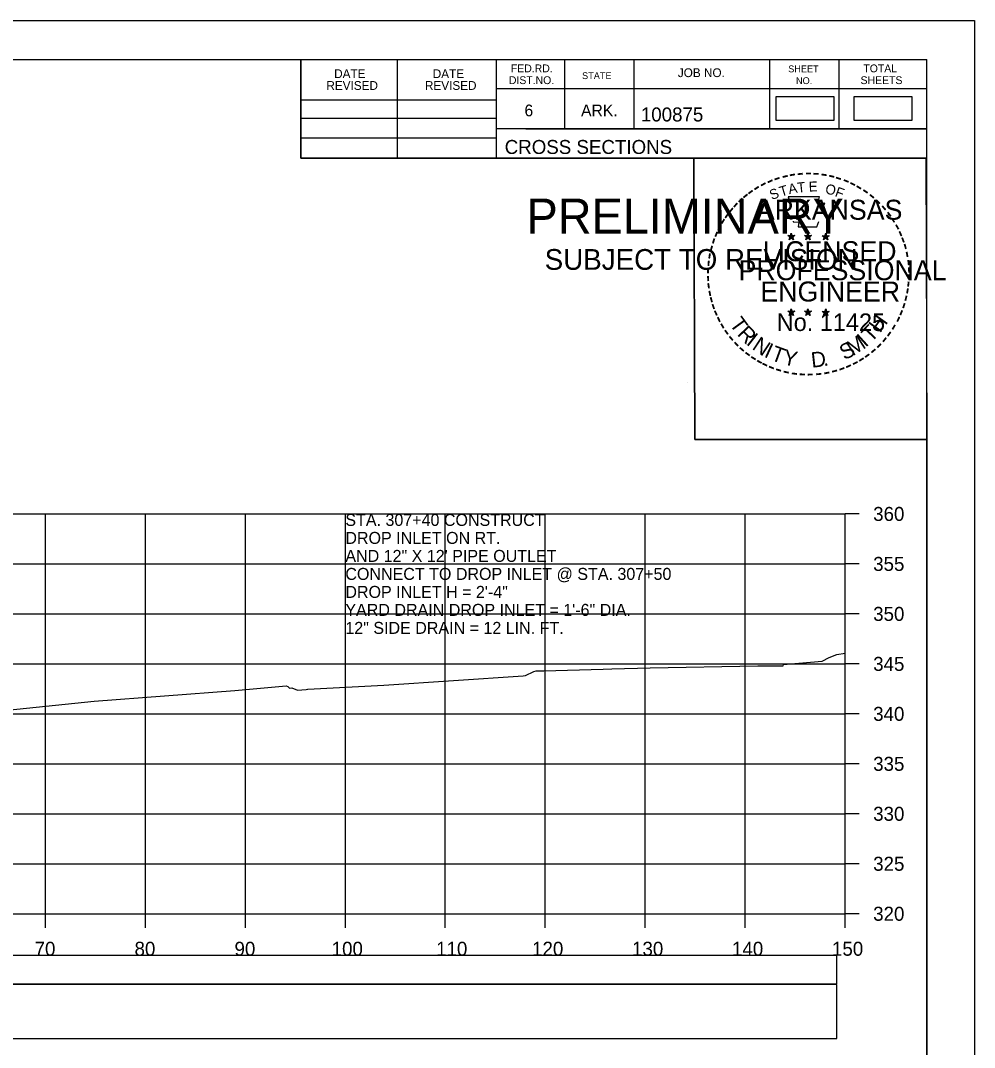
# Model space of a CAD drawing. Extents: x 1368122 to 1710785, y 373130 to 557566.
# Drawn here: x 1369423.1 to 1369518.5, y 373880.9 to 373983.7 of the extents above; entities that cross this region are included whole.
import ezdxf

# ---------------------------------------------------------------- set-up
doc = ezdxf.new("R2010")
doc.units = 0
for name, color, linetype in [('R_Axis', 7, 'Continuous'), ('R_Axis Annot', 7, 'Continuous'), ('R_Border', 7, 'Continuous'), ('R_Border PE', 7, 'Continuous'), ('R_Border Prem', 7, 'Continuous'), ('R_Drive', 7, 'Continuous'), ('R_Exist Surface', 7, 'Continuous'), ('R_Grid', 7, 'Continuous'), ('R_No Plot', 7, 'Continuous'), ('R_Water Annot', 7, 'Continuous')]:
    doc.layers.add(name, color=color, linetype=linetype)

msp = doc.modelspace()

# ---------------------------------------------------------------- linework, layer by layer
for points in [[(1369206.41, 373887.32), (1369504.71, 373887.32), (1369504.71, 373890.13), (1369206.41, 373890.13)], [(1369206.41, 373881.85), (1369504.71, 373881.85), (1369504.71, 373887.26), (1369206.41, 373887.26)]]:
    msp.add_lwpolyline(points, close=True)
at = {"layer": 'R_Axis'}
for p, q in [((1369505.56, 373894.32), (1369505.56, 373934.32)), ((1369506.96, 373934.32), (1369505.56, 373934.32)), ((1369506.96, 373929.32), (1369505.56, 373929.32)), ((1369506.96, 373924.32), (1369505.56, 373924.32)), ((1369506.96, 373919.32), (1369505.56, 373919.32)), ((1369506.96, 373914.32), (1369505.56, 373914.32)), ((1369506.96, 373909.32), (1369505.56, 373909.32)), ((1369506.96, 373904.32), (1369505.56, 373904.32)), ((1369506.96, 373899.32), (1369505.56, 373899.32)), ((1369205.56, 373894.32), (1369505.56, 373894.32)), ((1369425.56, 373892.92), (1369425.56, 373894.32)), ((1369435.56, 373892.92), (1369435.56, 373894.32)), ((1369445.56, 373892.92), (1369445.56, 373894.32)), ((1369455.56, 373892.92), (1369455.56, 373894.32)), ((1369465.56, 373892.92), (1369465.56, 373894.32)), ((1369475.56, 373892.92), (1369475.56, 373894.32)), ((1369485.56, 373892.92), (1369485.56, 373894.32)), ((1369495.56, 373892.92), (1369495.56, 373894.32)), ((1369505.56, 373892.92), (1369505.56, 373894.32)), ((1369506.96, 373894.32), (1369505.56, 373894.32))]:
    msp.add_line(p, q, dxfattribs=at)
at = {"layer": 'R_Border'}
for p, q in [((1369197.56, 373979.78), (1369513.74, 373979.78)), ((1369451.1, 373969.9), (1369451.1, 373979.78)), ((1369460.78, 373969.9), (1369460.78, 373979.78)), ((1369470.64, 373979.78), (1369470.64, 373969.9)), ((1369477.48, 373979.78), (1369477.48, 373972.84)), ((1369484.42, 373979.78), (1369484.42, 373972.84)), ((1369498, 373979.78), (1369498, 373972.84)), ((1369504.94, 373979.78), (1369504.94, 373972.84)), ((1369513.74, 373774.32), (1369513.74, 373979.78)), ((1369513.74, 373976.84), (1369470.64, 373976.84)), ((1369513.74, 373976.86), (1369513.74, 373976.86)), ((1369451.1, 373975.76), (1369470.64, 373975.76)), ((1369451.1, 373973.9), (1369470.64, 373973.9)), ((1369513.74, 373972.84), (1369470.64, 373972.84)), ((1369473.6, 373972.84), (1369513.74, 373972.84)), ((1369451.1, 373971.96), (1369470.64, 373971.96)), ((1369513.74, 373969.9), (1369451.1, 373969.9))]:
    msp.add_line(p, q, dxfattribs=at)
at = {"layer": 'R_Border PE'}
for p, q in [((1369500.17, 373962.41), (1369500.13, 373962.16)), ((1369500.17, 373962.05), (1369500.17, 373962.41)), ((1369500.17, 373962.41), (1369500.22, 373962.16)), ((1369501.84, 373962.41), (1369501.8, 373962.16)), ((1369501.84, 373962.05), (1369501.84, 373962.41)), ((1369501.84, 373962.41), (1369501.89, 373962.16)), ((1369503.61, 373962.4), (1369503.57, 373962.15)), ((1369503.61, 373962.04), (1369503.61, 373962.4)), ((1369503.61, 373962.4), (1369503.66, 373962.15)), ((1369499.83, 373962.16), (1369500.17, 373962.05)), ((1369499.83, 373962.16), (1369500.08, 373962.11)), ((1369499.83, 373962.16), (1369500.06, 373962.04)), ((1369499.96, 373961.75), (1369500.17, 373962.05)), ((1369499.96, 373961.75), (1369500.08, 373961.99)), ((1369499.96, 373961.75), (1369500.17, 373961.97)), ((1369500.52, 373962.16), (1369500.17, 373962.05)), ((1369500.39, 373961.75), (1369500.17, 373962.05)), ((1369500.39, 373961.75), (1369500.17, 373961.96)), ((1369500.52, 373962.16), (1369500.24, 373962.11)), ((1369500.39, 373961.75), (1369500.25, 373962.04)), ((1369500.52, 373962.16), (1369500.32, 373962.06)), ((1369501.5, 373962.16), (1369501.84, 373962.05)), ((1369501.5, 373962.16), (1369501.75, 373962.11)), ((1369501.5, 373962.16), (1369501.73, 373962.04)), ((1369501.63, 373961.75), (1369501.84, 373962.05)), ((1369501.63, 373961.75), (1369501.75, 373961.99)), ((1369501.63, 373961.75), (1369501.84, 373961.97)), ((1369502.19, 373962.16), (1369501.84, 373962.05)), ((1369502.06, 373961.75), (1369501.84, 373962.05)), ((1369502.06, 373961.75), (1369501.84, 373961.96)), ((1369502.19, 373962.16), (1369501.91, 373962.11)), ((1369502.06, 373961.75), (1369501.92, 373962.04)), ((1369502.19, 373962.16), (1369501.99, 373962.06)), ((1369503.26, 373962.15), (1369503.61, 373962.04)), ((1369503.26, 373962.15), (1369503.51, 373962.1)), ((1369503.26, 373962.15), (1369503.5, 373962.02)), ((1369503.39, 373961.74), (1369503.61, 373962.04)), ((1369503.39, 373961.74), (1369503.52, 373961.98)), ((1369503.39, 373961.74), (1369503.61, 373961.96)), ((1369503.96, 373962.15), (1369503.61, 373962.04)), ((1369503.82, 373961.74), (1369503.61, 373962.04)), ((1369503.82, 373961.74), (1369503.61, 373961.95)), ((1369503.96, 373962.15), (1369503.67, 373962.1)), ((1369503.82, 373961.74), (1369503.68, 373962.03)), ((1369503.96, 373962.15), (1369503.75, 373962.04)), ((1369499.82, 373954.59), (1369500.17, 373954.47)), ((1369499.82, 373954.59), (1369500.07, 373954.54)), ((1369499.82, 373954.59), (1369500.06, 373954.46)), ((1369499.95, 373954.18), (1369500.17, 373954.47)), ((1369499.95, 373954.18), (1369500.08, 373954.42)), ((1369499.95, 373954.18), (1369500.17, 373954.39)), ((1369500.17, 373954.84), (1369500.13, 373954.59)), ((1369500.17, 373954.47), (1369500.17, 373954.84)), ((1369500.17, 373954.84), (1369500.22, 373954.59)), ((1369500.52, 373954.59), (1369500.17, 373954.47)), ((1369500.38, 373954.18), (1369500.17, 373954.47)), ((1369500.38, 373954.18), (1369500.17, 373954.39)), ((1369500.52, 373954.59), (1369500.23, 373954.54)), ((1369500.38, 373954.18), (1369500.25, 373954.47)), ((1369500.52, 373954.59), (1369500.31, 373954.48)), ((1369501.49, 373954.59), (1369501.84, 373954.47)), ((1369501.49, 373954.59), (1369501.74, 373954.54)), ((1369501.49, 373954.59), (1369501.73, 373954.46)), ((1369501.62, 373954.18), (1369501.84, 373954.47)), ((1369501.62, 373954.18), (1369501.75, 373954.42)), ((1369501.62, 373954.18), (1369501.84, 373954.39)), ((1369501.84, 373954.84), (1369501.8, 373954.59)), ((1369501.84, 373954.47), (1369501.84, 373954.84)), ((1369501.84, 373954.84), (1369501.89, 373954.59)), ((1369502.19, 373954.59), (1369501.84, 373954.47)), ((1369502.05, 373954.18), (1369501.84, 373954.47)), ((1369502.05, 373954.18), (1369501.84, 373954.39)), ((1369502.19, 373954.59), (1369501.9, 373954.54)), ((1369502.05, 373954.18), (1369501.92, 373954.47)), ((1369502.19, 373954.59), (1369501.98, 373954.48)), ((1369503.26, 373954.58), (1369503.61, 373954.46)), ((1369503.26, 373954.58), (1369503.51, 373954.53)), ((1369503.26, 373954.58), (1369503.49, 373954.45)), ((1369503.39, 373954.17), (1369503.61, 373954.46)), ((1369503.39, 373954.17), (1369503.52, 373954.41)), ((1369503.39, 373954.17), (1369503.6, 373954.38)), ((1369503.61, 373954.83), (1369503.57, 373954.58)), ((1369503.82, 373954.17), (1369503.6, 373954.38)), ((1369503.61, 373954.46), (1369503.61, 373954.83)), ((1369503.61, 373954.83), (1369503.66, 373954.58)), ((1369503.95, 373954.58), (1369503.61, 373954.46)), ((1369503.82, 373954.17), (1369503.61, 373954.46)), ((1369503.95, 373954.58), (1369503.67, 373954.53)), ((1369503.82, 373954.17), (1369503.68, 373954.46)), ((1369503.95, 373954.58), (1369503.75, 373954.47))]:
    msp.add_line(p, q, dxfattribs=at)
for points in [[(1369499.87, 373966.04), (1369500.14, 373965.21)], [(1369503.38, 373965.11), (1369503.52, 373965.4), (1369502.83, 373965.37), (1369502.98, 373966.04), (1369499.87, 373966.04)], [(1369500.36, 373963.61), (1369500.36, 373963.53), (1369500.92, 373963.51), (1369500.87, 373963.03), (1369502.74, 373963.03), (1369502.94, 373963.57)], [(1369500.17, 373962.41), (1369500.39, 373961.75), (1369499.83, 373962.16), (1369500.52, 373962.16), (1369499.96, 373961.75), (1369500.17, 373962.41)], [(1369501.84, 373962.41), (1369502.06, 373961.75), (1369501.5, 373962.16), (1369502.19, 373962.16), (1369501.63, 373961.75), (1369501.84, 373962.41)], [(1369503.61, 373962.4), (1369503.82, 373961.74), (1369503.26, 373962.15), (1369503.96, 373962.15), (1369503.39, 373961.74), (1369503.61, 373962.4)], [(1369500.17, 373954.84), (1369500.38, 373954.18), (1369499.82, 373954.59), (1369500.52, 373954.59), (1369499.95, 373954.18), (1369500.17, 373954.84)], [(1369501.84, 373954.84), (1369502.05, 373954.18), (1369501.49, 373954.59), (1369502.19, 373954.59), (1369501.62, 373954.18), (1369501.84, 373954.84)], [(1369503.61, 373954.83), (1369503.82, 373954.17), (1369503.26, 373954.58), (1369503.95, 373954.58), (1369503.39, 373954.17), (1369503.61, 373954.83)]]:
    msp.add_lwpolyline(points, dxfattribs=at)
for centre, radius in [((1369500.17, 373962.05), 0.172), ((1369500.17, 373962.05), 0.145), ((1369501.84, 373962.05), 0.172), ((1369501.84, 373962.05), 0.145), ((1369503.61, 373962.03), 0.172), ((1369503.61, 373962.03), 0.145), ((1369500.17, 373962.05), 0.116), ((1369500.17, 373962.05), 0.0991), ((1369500.17, 373962.05), 0.0747), ((1369500.17, 373962.05), 0.0495), ((1369500.17, 373962.05), 0.0296), ((1369501.84, 373962.05), 0.116), ((1369501.84, 373962.05), 0.0991), ((1369501.84, 373962.05), 0.0747), ((1369501.84, 373962.05), 0.0495), ((1369501.84, 373962.05), 0.0296), ((1369503.61, 373962.03), 0.116), ((1369503.61, 373962.03), 0.0991), ((1369503.61, 373962.03), 0.0747), ((1369503.61, 373962.03), 0.0495), ((1369503.61, 373962.03), 0.0296), ((1369500.17, 373954.47), 0.172), ((1369500.17, 373954.47), 0.145), ((1369500.17, 373954.47), 0.116), ((1369500.17, 373954.47), 0.0991), ((1369500.17, 373954.47), 0.0747), ((1369500.17, 373954.47), 0.0495), ((1369500.17, 373954.47), 0.0296), ((1369501.84, 373954.47), 0.172), ((1369501.84, 373954.47), 0.145), ((1369501.84, 373954.47), 0.116), ((1369501.84, 373954.47), 0.0991), ((1369501.84, 373954.47), 0.0747), ((1369501.84, 373954.47), 0.0495), ((1369501.84, 373954.47), 0.0296), ((1369503.61, 373954.46), 0.172), ((1369503.61, 373954.46), 0.145), ((1369503.61, 373954.46), 0.116), ((1369503.61, 373954.46), 0.0991), ((1369503.61, 373954.46), 0.0747), ((1369503.61, 373954.46), 0.0495), ((1369503.61, 373954.46), 0.0296)]:
    msp.add_circle(centre, radius, dxfattribs=at)
at = {"layer": 'R_Drive'}
for points in [[(1369498.61, 373973.72), (1369504.45, 373973.72), (1369504.45, 373976.03), (1369498.61, 373976.03)], [(1369506.42, 373973.72), (1369512.26, 373973.72), (1369512.26, 373976.03), (1369506.42, 373976.03)]]:
    msp.add_lwpolyline(points, close=True, dxfattribs=at)
at = {"layer": 'R_Exist Surface'}
msp.add_lwpolyline([(1369420.72, 373914.58), (1369430.42, 373915.58), (1369444.49, 373916.66), (1369449.64, 373917.11), (1369449.82, 373917.04), (1369449.98, 373916.9), (1369450.19, 373916.91), (1369450.76, 373916.69), (1369451.64, 373916.77), (1369451.78, 373916.79), (1369451.79, 373916.79), (1369459.41, 373917.2), (1369473.34, 373918.12), (1369473.57, 373918.16), (1369474.4, 373918.56), (1369474.4, 373918.56), (1369474.66, 373918.63), (1369474.67, 373918.64), (1369474.68, 373918.64), (1369475.41, 373918.64), (1369481.34, 373918.78), (1369482.21, 373918.81), (1369486.06, 373918.93), (1369496.83, 373919.11), (1369497.87, 373919.12), (1369499.34, 373919.13), (1369499.39, 373919.26), (1369499.39, 373919.28), (1369499.75, 373919.28), (1369503.27, 373919.6), (1369503.95, 373919.96), (1369504.74, 373920.27), (1369505.56, 373920.38)], dxfattribs=at)
at = {"layer": 'R_Grid'}
for p, q in [((1369205.56, 373934.32), (1369505.56, 373934.32)), ((1369425.56, 373894.32), (1369425.56, 373934.32)), ((1369435.56, 373894.32), (1369435.56, 373934.32)), ((1369445.56, 373894.32), (1369445.56, 373934.32)), ((1369455.56, 373894.32), (1369455.56, 373934.32)), ((1369465.56, 373894.32), (1369465.56, 373934.32)), ((1369475.56, 373894.32), (1369475.56, 373934.32)), ((1369485.56, 373894.32), (1369485.56, 373934.32)), ((1369495.56, 373894.32), (1369495.56, 373934.32)), ((1369505.56, 373894.32), (1369505.56, 373934.32)), ((1369205.56, 373929.32), (1369505.56, 373929.32)), ((1369205.56, 373924.32), (1369505.56, 373924.32)), ((1369205.56, 373919.32), (1369505.56, 373919.32)), ((1369205.56, 373914.32), (1369505.56, 373914.32)), ((1369205.56, 373909.32), (1369505.56, 373909.32)), ((1369205.56, 373904.32), (1369505.56, 373904.32)), ((1369205.56, 373899.32), (1369505.56, 373899.32)), ((1369205.56, 373894.32), (1369505.56, 373894.32))]:
    msp.add_line(p, q, dxfattribs=at)
at = {"layer": 'R_No Plot'}
for p, q in [((1369185.16, 373983.68), (1369518.49, 373983.68)), ((1369489.77, 373947.45), (1369489.77, 373947.45))]:
    msp.add_line(p, q, dxfattribs=at)
for points in [[(1369185.15, 373983.68), (1369518.49, 373983.68), (1369518.49, 373770.34), (1369185.15, 373770.34)], [(1369431.48, 373979.78), (1369451.1, 373979.78), (1369451.1, 373969.9), (1369467.21, 373969.9), (1369490.41, 373969.9), (1369490.53, 373941.75), (1369513.74, 373941.75), (1369513.74, 373774.32), (1369197.56, 373774.32), (1369197.56, 373979.78)], [(1369490.41, 373969.9), (1369513.62, 373969.9), (1369513.74, 373941.75), (1369490.53, 373941.75)]]:
    msp.add_lwpolyline(points, close=True, dxfattribs=at)

# ---------------------------------------------------------------- texts
at = {"layer": 'R_Axis Annot'}
for s, p in [('360', (1369508.36, 373933.62)), ('355', (1369508.36, 373928.62)), ('350', (1369508.36, 373923.62)), ('345', (1369508.36, 373918.62)), ('340', (1369508.36, 373913.62)), ('335', (1369508.36, 373908.62)), ('330', (1369508.36, 373903.62)), ('325', (1369508.36, 373898.62)), ('320', (1369508.36, 373893.62)), ('70', (1369424.47, 373890.12)), ('80', (1369434.47, 373890.12)), ('90', (1369444.47, 373890.12)), ('100', (1369454.19, 373890.12)), ('110', (1369464.64, 373890.12)), ('120', (1369474.24, 373890.12)), ('130', (1369484.24, 373890.12)), ('140', (1369494.24, 373890.12)), ('150', (1369504.24, 373890.12))]:
    msp.add_text(s, height=1.4, dxfattribs=at).set_placement(p)
at = {"layer": 'R_Border'}
for s, height, p in [('DATE', 0.879, (1369454.44, 373977.92)), ('DATE', 0.879, (1369464.3, 373977.92)), ('FED.RD.', 0.782, (1369472.12, 373978.5)), ('JOB NO.', 0.879, (1369488.82, 373978.02)), ('SHEET', 0.684, (1369499.86, 373978.5)), ('TOTAL', 0.782, (1369507.38, 373978.5)), ('REVISED', 0.879, (1369453.66, 373976.74)), ('REVISED', 0.879, (1369463.52, 373976.74)), ('DIST.NO.', 0.782, (1369471.92, 373977.32)), ('STATE', 0.684, (1369479.24, 373977.82)), ('NO.', 0.684, (1369500.64, 373977.32)), ('SHEETS', 0.782, (1369507.1, 373977.32)), ('6', 1.17, (1369473.48, 373974.1)), ('ARK.', 1.172, (1369479.14, 373974.1)), ('100875', 1.4, (1369485.12, 373973.58)), ('CROSS SECTIONS', 1.4, (1369471.5, 373970.33))]:
    msp.add_text(s, height=height, rotation=360, dxfattribs=at).set_placement(p)
at = {"layer": 'R_Border PE'}
for s, height, rotation, p in [('-', 1.6, 10.2193, (1369500.04, 373967.57)), ('-', 1.6, 5.8968, (1369500.77, 373967.68)), ('-', 1.6, 0.1862, (1369501.54, 373967.75)), ('-', 1.6, 357.743, (1369502.27, 373967.74)), ('-', 1.6, 352.1617, (1369503.01, 373967.68)), ('-', 1.6, 28.7918, (1369497.35, 373966.58)), ('-', 1.6, 24.3072, (1369497.98, 373966.89)), ('-', 1.6, 19.1761, (1369498.61, 373967.16)), ('-', 1.6, 13.6301, (1369499.36, 373967.4)), ('A', 1, 11.2132, (1369499.96, 373966.3)), ('T', 1, 6.0228, (1369500.81, 373966.46)), ('E', 1, 0.8323, (1369501.92, 373966.57)), ('O', 1, 350.4515, (1369503.52, 373966.36)), ('-', 1.6, 347.2049, (1369503.73, 373967.57)), ('-', 1.6, 342.3362, (1369504.36, 373967.41)), ('-', 1.6, 337.8551, (1369505.1, 373967.19)), ('-', 1.6, 334.1211, (1369505.73, 373966.92)), ('-', 1.6, 38.9507, (1369495.7, 373965.43)), ('-', 1.6, 36.2317, (1369496.17, 373965.81)), ('-', 1.6, 34.0636, (1369496.75, 373966.21)), ('S', 1, 21.594, (1369498.22, 373965.71)), ('T', 1, 16.4036, (1369499.14, 373966.05)), ('F', 1, 340.0707, (1369504.47, 373966.13)), ('-', 1.6, 329.6409, (1369506.31, 373966.63)), ('-', 1.6, 325.8627, (1369506.95, 373966.27)), ('-', 1.6, 320.5297, (1369507.56, 373965.85)), ('-', 1.6, 48.423, (1369494.82, 373964.54)), ('-', 1.6, 42.9622, (1369495.26, 373965.02)), ('ARKANSAS', 2, 360, (1369496.72, 373963.75)), ('-', 1.6, 315.5786, (1369508.16, 373965.36)), ('-', 1.6, 54.2325, (1369494, 373963.49)), ('-', 1.6, 50.6142, (1369494.41, 373964.05)), ('-', 1.6, 309.8797, (1369508.73, 373964.81)), ('-', 1.6, 306.6522, (1369509.26, 373964.21)), ('-', 1.6, 62.8713, (1369493.36, 373962.35)), ('-', 1.6, 58.0706, (1369493.67, 373962.96)), ('-', 1.4, 303.6753, (1369509.74, 373963.64)), ('-', 1.6, 299.6684, (1369510.06, 373963.03)), ('-', 1.6, 67.7743, (1369493.1, 373961.73)), ('-', 1.6, 294.6628, (1369510.38, 373962.42)), ('-', 1.6, 75.461, (1369492.69, 373960.39)), ('-', 1.6, 72.3945, (1369492.88, 373961.1)), ('LICENSED', 2, 360, (1369497.32, 373959.6)), ('DWB', 0.01, 360, (1369500.16, 373962.04)), ('DWB', 0.01, 360, (1369501.83, 373962.04)), ('DWB', 0.01, 360, (1369503.6, 373962.03)), ('-', 1.6, 290.5728, (1369510.64, 373961.84)), ('-', 1.6, 285.1233, (1369510.88, 373961.26)), ('-', 1.6, 81.2013, (1369492.55, 373959.68)), ('-', 1.6, 280.5493, (1369511.08, 373960.52)), ('-', 1.6, 85.1863, (1369492.48, 373958.99)), ('PROFESSIONAL', 2, 360, (1369494.89, 373957.7)), ('-', 1.6, 276.5962, (1369511.24, 373959.75)), ('-', 1.6, 94.1959, (1369492.49, 373957.56)), ('-', 1.6, 89.0622, (1369492.45, 373958.29)), ('-', 1.6, 274.3301, (1369511.3, 373959.03)), ('-', 1.6, 269.9407, (1369511.33, 373958.4)), ('-', 1.6, 98.9479, (1369492.56, 373956.89)), ('ENGINEER', 2, 360, (1369497.08, 373955.57)), ('-', 1.6, 263.5172, (1369511.31, 373957.73)), ('-', 1.6, 101.7149, (1369492.7, 373956.16)), ('-', 1.6, 105.4578, (1369492.86, 373955.57)), ('-', 1.6, 255.7626, (1369511.13, 373956.4)), ('-', 1.6, 260.9953, (1369511.24, 373957.08)), ('-', 1.6, 109.0874, (1369493.07, 373954.93)), ('-', 1.6, 252.8681, (1369510.95, 373955.68)), ('-', 1.6, 114.0643, (1369493.33, 373954.34)), ('-', 1.6, 115.7289, (1369493.63, 373953.72)), ('T', 1.54, 306.0406, (1369493.93, 373953.31)), ('No. 11425', 1.757, 360, (1369498.71, 373952.62)), ('DWB', 0.01, 360, (1369500.16, 373954.47)), ('DWB', 0.01, 360, (1369501.83, 373954.47)), ('DWB', 0.01, 360, (1369503.59, 373954.46)), ('H', 1.54, 54.6088, (1369509.05, 373952.35)), ('-', 1.6, 244.6197, (1369510.47, 373954.38)), ('-', 1.6, 247.8887, (1369510.73, 373955.01)), ('-', 1.6, 120.4471, (1369493.99, 373953.13)), ('R', 1.54, 314.005, (1369494.69, 373952.26)), ('T', 1.54, 46.6444, (1369508.16, 373951.41)), ('-', 1.6, 239.0712, (1369510.07, 373953.63)), ('-', 1.6, 125.8934, (1369494.39, 373952.57)), ('-', 1.6, 130.7181, (1369494.85, 373952.02)), ('I', 1.54, 321.9694, (1369495.59, 373951.33)), ('N', 1.54, 326.5002, (1369496.16, 373950.86)), ('M', 1.54, 32.6563, (1369506.31, 373950.08)), ('I', 1.54, 42.1136, (1369507.6, 373950.93)), ('-', 1.6, 231.2538, (1369509.24, 373952.41)), ('-', 1.6, 233.8452, (1369509.67, 373952.97)), ('-', 1.6, 134.2238, (1369495.37, 373951.48)), ('-', 1.6, 138.9338, (1369495.9, 373951.01)), ('I', 1.54, 335.3603, (1369497.37, 373950.08)), ('T', 1.54, 339.8912, (1369498.03, 373949.75)), ('S', 1.54, 26.9312, (1369505.48, 373949.67)), ('-', 1.6, 225.7653, (1369508.76, 373951.84)), ('-', 1.6, 144.6463, (1369496.45, 373950.61)), ('-', 1.6, 148.0898, (1369497.01, 373950.24)), ('Y', 1.54, 347.8556, (1369499.25, 373949.3)), ('D', 1.54, 6.3969, (1369502.23, 373948.94)), ('-', 1.6, 212.2491, (1369507.16, 373950.48)), ('-', 1.6, 215.7363, (1369507.69, 373950.86)), ('-', 1.6, 221.0851, (1369508.24, 373951.33)), ('-', 1.6, 151.5704, (1369497.59, 373949.91)), ('-', 1.6, 154.6002, (1369498.11, 373949.66)), ('-', 1.6, 158.5612, (1369498.74, 373949.41)), ('-', 1.6, 162.7983, (1369499.42, 373949.2)), ('.', 1.54, 13.7642, (1369503.42, 373949.07)), ('-', 1.6, 200.7184, (1369505.35, 373949.54)), ('-', 1.6, 204.2516, (1369505.97, 373949.81)), ('-', 1.6, 207.3568, (1369506.6, 373950.13)), ('-', 1.6, 167.5555, (1369500.14, 373949.03)), ('-', 1.6, 173.1155, (1369500.91, 373948.92)), ('-', 1.6, 176.5183, (1369501.66, 373948.87)), ('-', 1.6, 181.5918, (1369502.4, 373948.89)), ('-', 1.6, 185.8167, (1369503.21, 373948.96)), ('-', 1.6, 191.2858, (1369503.95, 373949.1)), ('-', 1.6, 195.4743, (1369504.68, 373949.3))]:
    msp.add_text(s, height=height, rotation=rotation, dxfattribs=at).set_placement(p)
at = {"layer": 'R_Border Prem'}
for s, height, p in [('PRELIMINARY', 3.5, (1369473.69, 373962.37)), ('DWB', 0.01, (1369474.44, 373964.22)), ('SUBJECT TO REVISION', 2.0751, (1369475.5, 373958.74))]:
    msp.add_text(s, height=height, rotation=360, dxfattribs=at).set_placement(p)
at = {"layer": 'R_Water Annot'}
for s, p in [('STA. 307+40 CONSTRUCT', (1369455.56, 373933.12)), ('DROP INLET ON RT.', (1369455.56, 373931.32)), ('AND 12" X 12\' PIPE OUTLET', (1369455.56, 373929.52)), ('CONNECT TO DROP INLET @ STA. 307+50', (1369455.56, 373927.72)), ('DROP INLET H = 2\'-4"', (1369455.56, 373925.92)), ('YARD DRAIN DROP INLET = 1\'-6" DIA.', (1369455.56, 373924.12)), ('12" SIDE DRAIN = 12 LIN. FT.', (1369455.56, 373922.32))]:
    msp.add_text(s, height=1.2, dxfattribs=at).set_placement(p)

doc.saveas('drawing.dxf')
